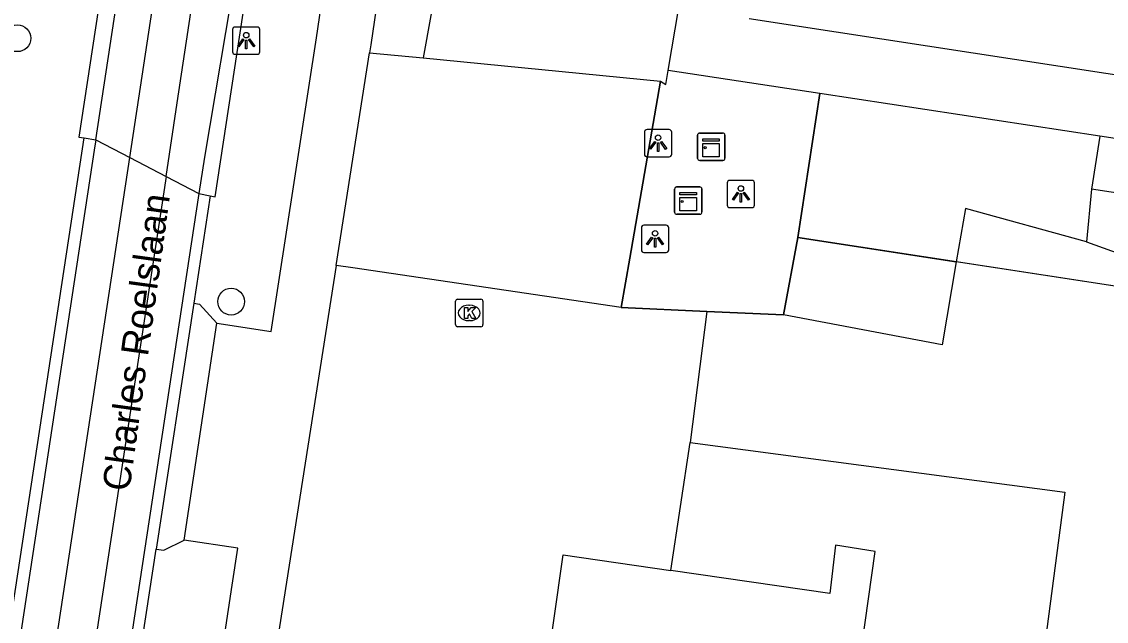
# Model space of a CAD drawing. Extents: x 161094 to 161705, y 379509 to 380907.
# Drawn here: x 161342.3 to 161381.89, y 380360.8 to 380382.7 of the extents above; entities that cross this region are included whole.
import ezdxf

# ---------------------------------------------------------------- set-up
doc = ezdxf.new("R2010")
doc.units = 0
for name, color, linetype in [('IMGEO_Berm_open', 7, 'Continuous'), ('IMGEO_Boom', 7, 'Continuous'), ('IMGEO_Groenvoorziening', 7, 'Continuous'), ('IMGEO_Hek', 7, 'Continuous'), ('IMGEO_Kast', 7, 'Continuous'), ('IMGEO_Kolk', 7, 'Continuous'), ('IMGEO_Lichtpunt', 7, 'Continuous'), ('IMGEO_Openbare_ruimte_label', 7, 'Continuous'), ('IMGEO_Pand', 7, 'Continuous'), ('IMGEO_Rijbaan_lokaal_gesloten', 7, 'Continuous'), ('IMGEO_Rijbaan_lokaal_open', 7, 'Continuous'), ('IMGEO_Voetpad_gesloten', 7, 'Continuous'), ('IMGEO_Voetpad_open', 7, 'Continuous')]:
    doc.layers.add(name, color=color, linetype=linetype)

msp = doc.modelspace()

# ---------------------------------------------------------------- linework, layer by layer
at = {"layer": 'IMGEO_Berm_open'}
for points in [[(161354.011, 380441.643), (161344.389, 380378.487), (161344.59, 380378.452)], [(161349.181, 380376.34), (161349.368, 380376.3), (161352.303, 380395.563)], [(161324.892, 380248.973), (161344.59, 380378.452)], [(161344.59, 380378.452), (161345.007, 380378.379)], [(161348.775, 380376.428), (161349.181, 380376.34)], [(161349.181, 380376.34), (161348.583, 380372.419)], [(161341.641, 380326.929), (161347.212, 380363.435)]]:
    msp.add_lwpolyline(points, dxfattribs=at)
at = {"layer": 'IMGEO_Boom'}
for centre in [(161342.145, 380382.093), (161349.949, 380372.477)]:
    msp.add_circle(centre, 0.489, dxfattribs=at)
at = {"layer": 'IMGEO_Groenvoorziening'}
msp.add_lwpolyline([(161359.874, 380397.513), (161356.953, 380381.374)], dxfattribs=at)
at = {"layer": 'IMGEO_Hek'}
for points in [[(161365.618, 380380.527), (161364.502, 380374.068)], [(161370.631, 380374.817), (161371.438, 380380.074)], [(161370.107, 380371.989), (161370.631, 380374.817)], [(161384.274, 380372.724), (161370.631, 380374.817)], [(161364.502, 380374.068), (161364.182, 380372.262)], [(161364.182, 380372.262), (161354.392, 380373.71)], [(161364.182, 380372.262), (161367.309, 380372.118)], [(161367.309, 380372.118), (161366.698, 380367.337)], [(161367.309, 380372.118), (161370.107, 380371.989)], [(161366.002, 380362.661), (161366.698, 380367.337)], [(161366.698, 380367.337), (161380.378, 380365.515), (161379.726, 380360.615), (161379.666, 380360.168)]]:
    msp.add_lwpolyline(points, dxfattribs=at)
at = {"layer": 'IMGEO_Kast'}
for p, q in [((161366.969, 380377.708), (161366.969, 380378.549)), ((161366.969, 380378.549), (161366.969, 380377.708)), ((161367.044, 380378.633), (161367.885, 380378.633)), ((161367.885, 380378.633), (161367.044, 380378.633)), ((161367.969, 380378.558), (161367.969, 380377.717)), ((161367.969, 380377.717), (161367.969, 380378.558)), ((161367.894, 380377.633), (161367.053, 380377.633)), ((161367.053, 380377.633), (161367.894, 380377.633)), ((161366.133, 380375.741), (161366.133, 380376.582)), ((161366.133, 380376.582), (161366.133, 380375.741)), ((161366.208, 380376.666), (161367.049, 380376.666)), ((161367.049, 380376.666), (161366.208, 380376.666)), ((161367.133, 380376.591), (161367.133, 380375.75)), ((161367.133, 380375.75), (161367.133, 380376.591)), ((161367.058, 380375.666), (161366.217, 380375.666)), ((161366.217, 380375.666), (161367.058, 380375.666))]:
    msp.add_line(p, q, dxfattribs=at)
for points in [[(161367.164, 380378.423), (161367.764, 380378.423), (161367.764, 380378.338), (161367.164, 380378.338), (161367.164, 380378.423)], [(161367.164, 380378.248), (161367.764, 380378.248), (161367.764, 380377.759), (161367.164, 380377.759), (161367.164, 380378.248)], [(161366.328, 380376.456), (161366.928, 380376.456), (161366.928, 380376.371), (161366.328, 380376.371), (161366.328, 380376.456)], [(161366.328, 380376.281), (161366.928, 380376.281), (161366.928, 380375.792), (161366.328, 380375.792), (161366.328, 380376.281)]]:
    msp.add_lwpolyline(points, dxfattribs=at)
for centre in [(161367.248, 380378.097), (161366.412, 380376.13)]:
    msp.add_circle(centre, 0.0377, dxfattribs=at)
for centre, start, end in [((161367.047, 380378.555), 92.4484, 184.2845), ((161367.047, 380378.555), 92.4484, 184.2845), ((161367.891, 380378.555), 2.4484, 94.2845), ((161367.891, 380378.555), 2.4484, 94.2845), ((161367.047, 380377.711), 182.4484, 274.2845), ((161367.047, 380377.711), 182.4484, 274.2845), ((161367.891, 380377.711), 272.4484, 4.2845), ((161367.891, 380377.711), 272.4484, 4.2845), ((161366.211, 380376.588), 92.4484, 184.2845), ((161366.211, 380376.588), 92.4484, 184.2845), ((161367.055, 380376.588), 2.4484, 94.2845), ((161367.055, 380376.588), 2.4484, 94.2845), ((161366.211, 380375.744), 182.4484, 274.2845), ((161366.211, 380375.744), 182.4484, 274.2845), ((161367.055, 380375.744), 272.4484, 4.2845), ((161367.055, 380375.744), 272.4484, 4.2845)]:
    msp.add_arc(centre, 0.0779, start, end, dxfattribs=at)
at = {"layer": 'IMGEO_Kolk'}
for p, q in [((161358.139, 380371.636), (161358.139, 380372.488)), ((161358.214, 380372.562), (161359.066, 380372.562)), ((161359.14, 380372.488), (161359.14, 380371.636)), ((161358.627, 380372.342), (161358.652, 380372.342)), ((161358.65, 380371.782), (161358.625, 380371.782)), ((161359.066, 380371.562), (161358.214, 380371.562))]:
    msp.add_line(p, q, dxfattribs=at)
for points in [[(161358.139, 380371.636), (161358.139, 380372.488)], [(161358.214, 380372.562), (161359.066, 380372.562)], [(161359.14, 380372.488), (161359.14, 380371.636)], [(161358.46, 380372.262), (161358.583, 380372.262), (161358.583, 380372.111), (161358.713, 380372.262), (161358.877, 380372.262), (161358.731, 380372.111), (161358.884, 380371.862), (161358.732, 380371.862), (161358.647, 380372.026), (161358.583, 380371.959), (161358.583, 380371.862), (161358.46, 380371.862), (161358.46, 380372.262)], [(161359.066, 380371.562), (161358.214, 380371.562)]]:
    msp.add_lwpolyline(points, dxfattribs=at)
for centre, start, end in [((161358.216, 380372.486), 91.552, 178.448), ((161358.216, 380372.486), 91.552, 178.448), ((161359.064, 380372.486), 1.552, 88.448), ((161359.064, 380372.486), 1.552, 88.448), ((161358.216, 380371.638), 181.552, 268.448), ((161358.216, 380371.638), 181.552, 268.448), ((161359.064, 380371.638), 271.552, 358.448), ((161359.064, 380371.638), 271.552, 358.448)]:
    msp.add_arc(centre, 0.0765, start, end, dxfattribs=at)
for centre, major_axis, ratio, start_param, end_param in [((161358.626, 380372.062), (-0.387, 0.002), 0.722429, 4.712389, 7.853982), ((161358.651, 380372.062), (-0.39, 0.002), 0.717154, 1.570796, 4.712389)]:
    msp.add_ellipse(centre, major_axis=major_axis, ratio=ratio, start_param=start_param, end_param=end_param, dxfattribs=at)
at = {"layer": 'IMGEO_Lichtpunt'}
for p, q in [((161350, 380382.408), (161350, 380381.601)), ((161350, 380382.408), (161350, 380381.601)), ((161350.902, 380382.503), (161350.094, 380382.503)), ((161350.902, 380382.503), (161350.094, 380382.503)), ((161350.996, 380381.601), (161350.996, 380382.408)), ((161350.996, 380381.601), (161350.996, 380382.408)), ((161350.094, 380381.507), (161350.902, 380381.507)), ((161350.094, 380381.507), (161350.902, 380381.507)), ((161365.033, 380378.664), (161365.033, 380377.857)), ((161365.033, 380378.664), (161365.033, 380377.857)), ((161365.935, 380378.759), (161365.127, 380378.759)), ((161365.935, 380378.759), (161365.127, 380378.759)), ((161366.029, 380377.857), (161366.029, 380378.664)), ((161366.029, 380377.857), (161366.029, 380378.664)), ((161365.127, 380377.763), (161365.935, 380377.763)), ((161365.127, 380377.763), (161365.935, 380377.763)), ((161368.956, 380376.904), (161368.148, 380376.904)), ((161368.956, 380376.904), (161368.148, 380376.904)), ((161368.054, 380376.809), (161368.054, 380376.002)), ((161368.054, 380376.809), (161368.054, 380376.002)), ((161369.05, 380376.002), (161369.05, 380376.809)), ((161369.05, 380376.002), (161369.05, 380376.809)), ((161368.148, 380375.908), (161368.956, 380375.908)), ((161368.148, 380375.908), (161368.956, 380375.908)), ((161365.824, 380375.267), (161365.016, 380375.267)), ((161365.824, 380375.267), (161365.016, 380375.267)), ((161364.922, 380375.172), (161364.922, 380374.365)), ((161364.922, 380375.172), (161364.922, 380374.365)), ((161365.918, 380374.365), (161365.918, 380375.172)), ((161365.918, 380374.365), (161365.918, 380375.172)), ((161365.016, 380374.271), (161365.824, 380374.271)), ((161365.016, 380374.271), (161365.824, 380374.271))]:
    msp.add_line(p, q, dxfattribs=at)
for points in [[(161350.374, 380382.072), (161350.413, 380382.044), (161350.225, 380381.782), (161350.187, 380381.809), (161350.374, 380382.072)], [(161350.476, 380382.024), (161350.523, 380382.024), (161350.523, 380381.702), (161350.476, 380381.702), (161350.476, 380382.024)], [(161350.586, 380382.044), (161350.624, 380382.071), (161350.811, 380381.809), (161350.772, 380381.781), (161350.586, 380382.044)], [(161365.407, 380378.328), (161365.446, 380378.3), (161365.258, 380378.038), (161365.22, 380378.065), (161365.407, 380378.328)], [(161365.509, 380378.28), (161365.556, 380378.28), (161365.556, 380377.958), (161365.509, 380377.958), (161365.509, 380378.28)], [(161365.619, 380378.3), (161365.657, 380378.327), (161365.844, 380378.065), (161365.805, 380378.037), (161365.619, 380378.3)], [(161368.428, 380376.473), (161368.467, 380376.445), (161368.279, 380376.183), (161368.241, 380376.21), (161368.428, 380376.473)], [(161368.53, 380376.425), (161368.577, 380376.425), (161368.577, 380376.103), (161368.53, 380376.103), (161368.53, 380376.425)], [(161368.64, 380376.445), (161368.678, 380376.472), (161368.865, 380376.21), (161368.826, 380376.182), (161368.64, 380376.445)], [(161365.296, 380374.836), (161365.335, 380374.808), (161365.147, 380374.546), (161365.109, 380374.573), (161365.296, 380374.836)], [(161365.398, 380374.788), (161365.445, 380374.788), (161365.445, 380374.466), (161365.398, 380374.466), (161365.398, 380374.788)], [(161365.508, 380374.808), (161365.546, 380374.835), (161365.733, 380374.573), (161365.694, 380374.545), (161365.508, 380374.808)]]:
    msp.add_lwpolyline(points, dxfattribs=at)
for centre in [(161350.499, 380382.206), (161365.532, 380378.462), (161368.553, 380376.607), (161365.421, 380374.97)]:
    msp.add_circle(centre, 0.0994, dxfattribs=at)
for centre, start, end in [((161350.094, 380382.408), 90, 180), ((161350.094, 380382.408), 90, 180), ((161350.902, 380382.408), 0, 90), ((161350.902, 380382.408), 0, 90), ((161350.094, 380381.601), 180, 270), ((161350.094, 380381.601), 180, 270), ((161350.902, 380381.601), 270, 0), ((161350.902, 380381.601), 270, 360), ((161365.127, 380378.664), 90, 180), ((161365.127, 380378.664), 90, 180), ((161365.935, 380378.664), 0, 90), ((161365.935, 380378.664), 0, 90), ((161365.127, 380377.857), 180, 270), ((161365.127, 380377.857), 180, 270), ((161365.935, 380377.857), 270, 0), ((161365.935, 380377.857), 270, 360), ((161368.148, 380376.809), 90, 180), ((161368.148, 380376.809), 90, 180), ((161368.956, 380376.809), 0, 90), ((161368.956, 380376.809), 0, 90), ((161368.148, 380376.002), 180, 270), ((161368.148, 380376.002), 180, 270), ((161368.956, 380376.002), 270, 0), ((161368.956, 380376.002), 270, 360), ((161365.016, 380375.172), 90, 180), ((161365.016, 380375.172), 90, 180), ((161365.824, 380375.172), 0, 90), ((161365.824, 380375.172), 0, 90), ((161365.016, 380374.365), 180, 270), ((161365.016, 380374.365), 180, 270), ((161365.824, 380374.365), 270, 0), ((161365.824, 380374.365), 270, 360)]:
    msp.add_arc(centre, 0.0946, start, end, dxfattribs=at)
at = {"layer": 'IMGEO_Pand'}
for points in [[(161356.908, 380327.082), (161366.611, 380325.623), (161367.399, 380330.984), (161368.807, 380330.788), (161369.309, 380334.25), (161370.031, 380334.145), (161371.822, 380346.414), (161371.074, 380346.522), (161371.541, 380349.758), (161370.129, 380349.999), (161371.606, 380360.303), (161372.782, 380360.137), (161372.742, 380359.915), (161372.961, 380359.891), (161373.459, 380363.357), (161372.008, 380363.588), (161371.8, 380361.818), (161366.002, 380362.661)], [(161354.512, 380357.063), (161361.053, 380356.126), (161362.072, 380363.233), (161366.002, 380362.661)]]:
    msp.add_lwpolyline(points, dxfattribs=at)
at = {"layer": 'IMGEO_Rijbaan_lokaal_gesloten'}
for points in [[(161346.249, 380377.736), (161347.339, 380384.899), (161352.727, 380420.46), (161357.973, 380455.328), (161359.092, 380463.074)], [(161347.572, 380377.051), (161347.982, 380379.737), (161354.389, 380422.138), (161360.548, 380462.859)], [(161345.007, 380378.379), (161355.725, 380448.967), (161357.571, 380461.128)], [(161361.586, 380460.548), (161359.751, 380448.386), (161350.135, 380384.631), (161348.977, 380377.751), (161348.775, 380376.428)], [(161345.007, 380378.379), (161344.951, 380378.008), (161322.076, 380227.626), (161321.656, 380227.7)], [(161345.007, 380378.379), (161346.249, 380377.736)], [(161347.572, 380377.051), (161337.64, 380311.897), (161331.61, 380272.482), (161327.257, 380243.533), (161322.079, 380209.661), (161318.978, 380188.612), (161317.471, 380188.836), (161329.956, 380271.064), (161337.144, 380317.912), (161346.249, 380377.736)], [(161347.572, 380377.051), (161348.775, 380376.428)], [(161348.775, 380376.428), (161335.506, 380289.381), (161325.446, 380223.42)]]:
    msp.add_lwpolyline(points, dxfattribs=at)
at = {"layer": 'IMGEO_Rijbaan_lokaal_open'}
msp.add_lwpolyline([(161346.249, 380377.736), (161347.572, 380377.051)], dxfattribs=at)
at = {"layer": 'IMGEO_Voetpad_gesloten'}
for points in [[(161365.899, 380380.919), (161366.293, 380383.221)], [(161368.855, 380382.814), (161399.728, 380378.077)], [(161371.438, 380380.074), (161365.899, 380380.919)], [(161381.648, 380378.516), (161371.438, 380380.074)], [(161468.018, 380365.334), (161381.648, 380378.516)], [(161381.163, 380374.657), (161376.746, 380375.877), (161376.415, 380373.93)], [(161381.163, 380374.657), (161382.693, 380374.109), (161384.386, 380373.456), (161384.274, 380372.724)], [(161353.781, 380373.8), (161351.226, 380357.502)], [(161364.182, 380372.262), (161354.392, 380373.71), (161353.781, 380373.8)], [(161376.415, 380373.93), (161375.899, 380370.898), (161370.107, 380371.989)], [(161384.274, 380372.724), (161376.415, 380373.93)], [(161367.309, 380372.118), (161364.182, 380372.262)], [(161367.309, 380372.118), (161366.698, 380367.337)], [(161370.107, 380371.989), (161367.309, 380372.118)], [(161366.002, 380362.661), (161366.698, 380367.337)], [(161366.698, 380367.337), (161380.378, 380365.515), (161379.726, 380360.615), (161379.666, 380360.168)]]:
    msp.add_lwpolyline(points, dxfattribs=at)
at = {"layer": 'IMGEO_Voetpad_open'}
for points in [[(161349.424, 380371.695), (161351.411, 380371.391), (161353.061, 380382.104), (161353.938, 380388.06), (161354.108, 380389.079)], [(161356.103, 380388.816), (161355.909, 380387.739), (161355.043, 380381.85), (161354.998, 380381.564)], [(161353.781, 380373.8), (161354.998, 380381.564)], [(161354.998, 380381.564), (161356.953, 380381.374)], [(161356.953, 380381.374), (161365.618, 380380.527)], [(161365.618, 380380.527), (161365.81, 380380.399), (161365.899, 380380.919)], [(161364.182, 380372.262), (161364.502, 380374.068), (161365.618, 380380.527)], [(161371.438, 380380.074), (161370.631, 380374.817)], [(161381.648, 380378.516), (161381.353, 380376.586)], [(161381.353, 380376.586), (161381.163, 380374.657)], [(161471.162, 380362.866), (161384.783, 380376.062), (161381.353, 380376.586)], [(161370.631, 380374.817), (161370.107, 380371.989)], [(161370.631, 380374.817), (161376.415, 380373.93)], [(161348.583, 380372.419), (161347.212, 380363.435)], [(161348.583, 380372.419), (161348.788, 380372.383), (161349.424, 380371.695)], [(161348.24, 380363.761), (161349.424, 380371.695)], [(161344.627, 380326.528), (161349.991, 380362.127), (161350.192, 380363.472), (161348.24, 380363.761)], [(161347.212, 380363.435), (161347.497, 380363.399), (161348.24, 380363.761)]]:
    msp.add_lwpolyline(points, dxfattribs=at)

# ---------------------------------------------------------------- texts
at = {"layer": 'IMGEO_Openbare_ruimte_label'}
msp.add_text('Charles Roelslaan', height=1, rotation=82.1858, dxfattribs=at).set_placement((161346.232, 380365.517))

doc.saveas('drawing.dxf')
